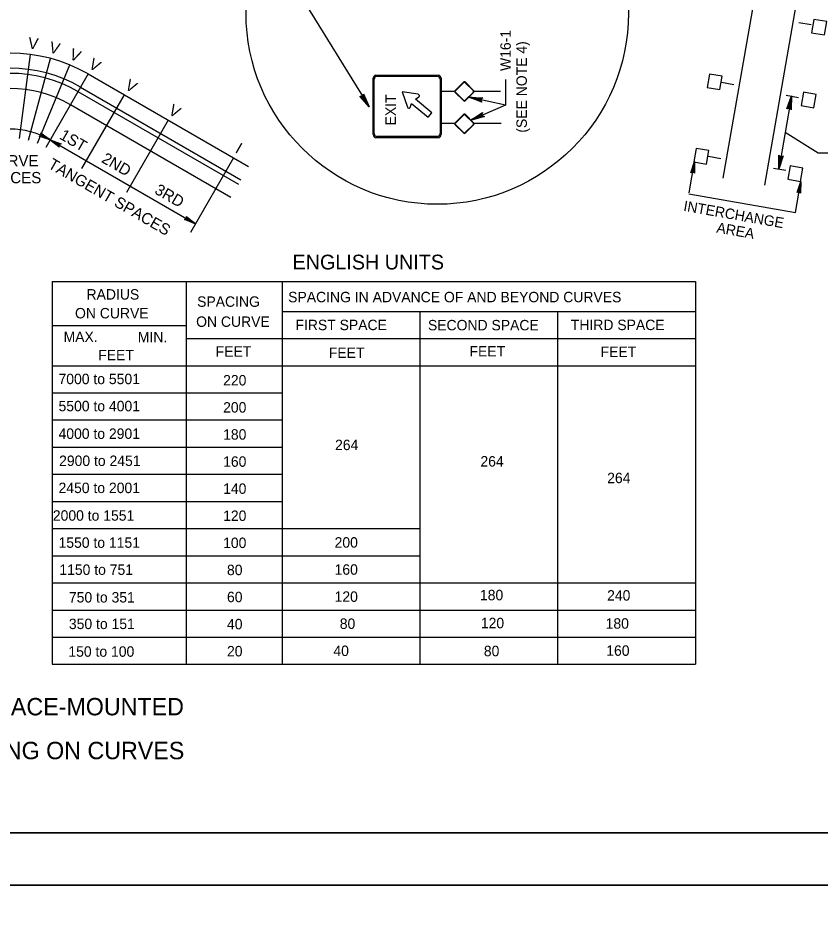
# Model space of a CAD drawing. Extents: x 640253 to 641999, y 298458 to 299646.
# Drawn here: x 641345.5 to 641576.3, y 299044.1 to 299301.1 of the extents above; entities that cross this region are included whole.
import ezdxf

# ---------------------------------------------------------------- set-up
doc = ezdxf.new("R2010")
doc.units = 0
for name, color, linetype in [('1', 7, 'Continuous'), ('2', 7, 'Continuous'), ('PLT-BNDY', 7, 'Continuous')]:
    doc.layers.add(name, color=color, linetype=linetype)

msp = doc.modelspace()

# ---------------------------------------------------------------- linework, layer by layer
at = {"layer": '1'}
for p, q in [((641447.76, 299267.56), (641447.76, 299283.76)), ((641448.05, 299267.83), (641448.05, 299283.49)), ((641448.54, 299284.66), (641466.48, 299284.66)), ((641448.77, 299284.33), (641466.25, 299284.33)), ((641466.97, 299283.49), (641466.97, 299267.83)), ((641467.26, 299283.76), (641467.26, 299267.56)), ((641471.26, 299280.16), (641473.79, 299282.69)), ((641471.39, 299280.15), (641473.81, 299282.56)), ((641474.16, 299282.56), (641476.58, 299280.15)), ((641474.18, 299282.69), (641476.71, 299280.16)), ((641471.18, 299279.96), (641466.97, 299279.96)), ((641484.35, 299279.96), (641476.79, 299279.96)), ((641460.69, 299279.14), (641456.07, 299279.87)), ((641456.07, 299279.87), (641457.61, 299275.45)), ((641459.89, 299277.79), (641460.91, 299278.41)), ((641464.62, 299273.86), (641459.89, 299277.79)), ((641473.79, 299277.24), (641471.26, 299279.77)), ((641473.81, 299277.37), (641471.39, 299279.79)), ((641476.58, 299279.79), (641474.16, 299277.37)), ((641476.71, 299279.77), (641474.18, 299277.24)), ((641458.38, 299275.37), (641458.79, 299276.49)), ((641458.79, 299276.49), (641463.53, 299272.55)), ((641463.53, 299272.55), (641464.62, 299273.86)), ((641471.26, 299270.85), (641473.79, 299273.39)), ((641471.39, 299270.84), (641473.81, 299273.26)), ((641474.16, 299273.26), (641476.58, 299270.84)), ((641474.18, 299273.39), (641476.71, 299270.85)), ((641471.18, 299270.7), (641466.97, 299270.7)), ((641473.79, 299267.93), (641471.26, 299270.47)), ((641473.81, 299268.06), (641471.39, 299270.48)), ((641476.58, 299270.48), (641474.16, 299268.06)), ((641476.71, 299270.47), (641474.18, 299267.93)), ((641484.56, 299270.7), (641476.79, 299270.7)), ((641466.48, 299266.66), (641448.54, 299266.66)), ((641466.25, 299267), (641448.77, 299267)), ((641920.31, 299066.63), (641134.31, 299066.63)), ((641134.31, 299066.63), (641720.31, 299066.63))]:
    msp.add_line(p, q, dxfattribs=at)
for centre, radius, start, end in [((641473.99, 299282.5), 0.275, 45, 135), ((641473.99, 299282.38), 0.252, 45, 135), ((641471.46, 299279.97), 0.275, 135, 225), ((641471.57, 299279.97), 0.252, 135, 225), ((641476.4, 299279.97), 0.252, 315, 45), ((641476.52, 299279.97), 0.275, 315, 45), ((641473.99, 299277.44), 0.275, 225, 315), ((641473.99, 299277.55), 0.252, 225, 315), ((641473.99, 299273.19), 0.275, 45, 135), ((641473.99, 299273.08), 0.252, 45, 135), ((641471.46, 299270.66), 0.275, 135, 225), ((641471.57, 299270.66), 0.252, 135, 225), ((641476.4, 299270.66), 0.252, 315, 45), ((641476.52, 299270.66), 0.275, 315, 45), ((641473.99, 299268.13), 0.275, 225, 315), ((641473.99, 299268.24), 0.252, 225, 315)]:
    msp.add_arc(centre, radius, start, end, dxfattribs=at)
for centre, major_axis, start_param, end_param in [((641448.54, 299283.76), (0, -0.9), 3.141593, 4.712389), ((641448.77, 299283.49), (0, -0.833), 3.141593, 4.712389), ((641466.25, 299283.49), (0, 0.833), 4.712389, 6.283185), ((641466.48, 299283.76), (0, 0.9), 4.712389, 6.283185), ((641460.66, 299278.75), (0.336, -0.279), 6.014589, 8.386103), ((641457.99, 299275.56), (-0.339, 0.282), 1.019875, 3.40872), ((641448.54, 299267.56), (0, -0.9), 4.712389, 6.283185), ((641448.77, 299267.83), (0, -0.833), 4.712389, 6.283185), ((641466.25, 299267.83), (0, 0.833), 3.141593, 4.712389), ((641466.48, 299267.56), (0, 0.9), 3.141593, 4.712389)]:
    msp.add_ellipse(centre, major_axis=major_axis, ratio=0.866667, start_param=start_param, end_param=end_param, dxfattribs=at)
at = {"layer": '2'}
for p, q in [((641548.4, 299255.06), (641564.23, 299345.46)), ((641560.38, 299252.96), (641575.95, 299342.02)), ((641421.94, 299315.4), (641446.55, 299275.57)), ((641570.22, 299299.84), (641570.22, 299299.84)), ((641570.22, 299299.84), (641573.75, 299299.22)), ((641345.98, 299266.45), (641349.15, 299290.63)), ((641348.59, 299265.92), (641354.9, 299289.48)), ((641351.14, 299265.06), (641360.47, 299287.59)), ((641365.73, 299284.99), (641353.56, 299263.87)), ((641365.73, 299284.99), (641411.88, 299258.34)), ((641485.84, 299283.45), (641485.84, 299276.05)), ((641363.56, 299281.22), (641409.71, 299254.58)), ((641551.46, 299281.88), (641547.94, 299282.5)), ((641551.46, 299281.88), (641551.46, 299281.88)), ((641362.81, 299279.93), (641408.96, 299253.29)), ((641376.07, 299279.03), (641363.84, 299257.8)), ((641485.84, 299276.05), (641475.26, 299278.32)), ((641568.09, 299278.74), (641564.39, 299257.61)), ((641566.56, 299278.89), (641566.56, 299278.89)), ((641566.56, 299278.89), (641570.08, 299278.27)), ((641360.64, 299276.17), (641406.79, 299249.53)), ((641485.84, 299276.05), (641475.82, 299271.75)), ((641388.76, 299271.71), (641376.78, 299250.93)), ((641575.72, 299262.19), (641566.24, 299268.18)), ((641354.81, 299266.05), (641396.62, 299241.9)), ((641407.56, 299260.88), (641395.18, 299239.4)), ((641538.63, 299250.84), (641540.19, 299259.77)), ((641547.73, 299260.6), (641544.2, 299261.22)), ((641547.73, 299260.6), (641547.73, 299260.6)), ((641562.9, 299257.94), (641562.9, 299257.94)), ((641562.9, 299257.94), (641566.42, 299257.32)), ((641560.38, 299252.96), (641560.38, 299252.96)), ((641569.2, 299245.13), (641570.76, 299254.06)), ((641538.53, 299250.5), (641569.2, 299245.13)), ((641355.44, 299225.24), (641355.44, 299115.14)), ((641355.44, 299225.24), (641540.45, 299225.24)), ((641393.93, 299225.24), (641393.93, 299115.14)), ((641421.58, 299225.24), (641421.58, 299115.14)), ((641540.45, 299225.24), (641540.45, 299115.14)), ((641421.58, 299216.68), (641540.45, 299216.68)), ((641426.39, 299216.68), (641426.39, 299216.68)), ((641461.18, 299216.68), (641461.18, 299115.14)), ((641461.73, 299216.68), (641461.73, 299216.68)), ((641497.07, 299216.68), (641497.07, 299216.68)), ((641500.78, 299216.68), (641500.78, 299115.14)), ((641532.41, 299216.68), (641532.41, 299216.68)), ((641355.44, 299212.58), (641394, 299212.58)), ((641393.93, 299208.87), (641540.45, 299208.87)), ((641355.44, 299201.06), (641540.45, 299201.06)), ((641355.44, 299193.25), (641421.58, 299193.25)), ((641355.44, 299185.44), (641421.58, 299185.44)), ((641355.44, 299177.63), (641421.58, 299177.63)), ((641355.44, 299169.82), (641421.58, 299169.82)), ((641355.44, 299162.01), (641421.58, 299162.01)), ((641355.44, 299154.2), (641461.18, 299154.2)), ((641355.44, 299146.38), (641461.18, 299146.38)), ((641355.44, 299138.57), (641540.45, 299138.57)), ((641355.44, 299130.76), (641540.45, 299130.76)), ((641355.44, 299122.95), (641540.45, 299122.95)), ((641355.44, 299115.14), (641540.45, 299115.14))]:
    msp.add_line(p, q, dxfattribs=at)
for points in [[(641577.55, 299296.22), (641578.22, 299300.06), (641574.53, 299300.71), (641573.85, 299296.87)], [(641547.5, 299280.48), (641548.17, 299284.32), (641544.48, 299284.97), (641543.81, 299281.13)], [(641574.52, 299275.23), (641575.19, 299279.07), (641571.5, 299279.72), (641570.83, 299275.88)], [(641543.67, 299259.09), (641544.34, 299262.93), (641540.65, 299263.57), (641539.98, 299259.73)], [(641570.69, 299254.04), (641571.36, 299257.88), (641567.67, 299258.53), (641567, 299254.69)]]:
    msp.add_lwpolyline(points, close=True, dxfattribs=at)
for points in [[(641444.9, 299279), (641444.75, 299278.74), (641446.55, 299275.57), (641444.9, 299279), (641444.93, 299279.26), (641446.55, 299275.57), (641444.43, 299278.53), (641444.13, 299278.49), (641446.55, 299275.57), (641443.87, 299278.57), (641444.13, 299278.49)], [(641478.86, 299277.06), (641478.78, 299277.36), (641475.26, 299278.32), (641478.86, 299277.06), (641479.01, 299276.86), (641475.26, 299278.32), (641478.86, 299277.74), (641479.04, 299277.97), (641475.26, 299278.32), (641479.28, 299278.1), (641479.04, 299277.97)], [(641566.97, 299275.09), (641567.26, 299275.18), (641568.09, 299278.74), (641566.97, 299275.09), (641566.77, 299274.93), (641568.09, 299278.74), (641567.64, 299275.12), (641567.88, 299274.94), (641568.09, 299278.74), (641568.03, 299274.71), (641567.88, 299274.94)], [(641479.49, 299272.79), (641479.25, 299272.99), (641475.82, 299271.75), (641479.49, 299272.79), (641479.73, 299272.72), (641475.82, 299271.75), (641479.1, 299273.34), (641479.11, 299273.64), (641475.82, 299271.75), (641479.23, 299273.89), (641479.11, 299273.64)], [(641352.17, 299267.84), (641352.17, 299267.58), (641354.81, 299266.05), (641352.17, 299267.84), (641352.1, 299268.03), (641354.81, 299266.05), (641352.03, 299267.28), (641351.84, 299267.14), (641354.81, 299266.05), (641351.62, 299267.07), (641351.84, 299267.14)], [(641357.34, 299264.12), (641357.36, 299264.38), (641354.81, 299266.05), (641357.34, 299264.12), (641357.41, 299263.93), (641354.81, 299266.05), (641357.52, 299264.66), (641357.73, 299264.8), (641354.81, 299266.05), (641357.95, 299264.85), (641357.73, 299264.8)], [(641608.47, 299262.19), (641575.72, 299262.19)], [(641539.26, 299256.73), (641539.5, 299256.8), (641540.19, 299259.77), (641539.26, 299256.73), (641539.1, 299256.59), (641540.19, 299259.77), (641539.81, 299256.75), (641540.02, 299256.61), (641540.19, 299259.77), (641540.14, 299256.42), (641540.02, 299256.61)], [(641565.51, 299261.26), (641565.22, 299261.17), (641564.39, 299257.61), (641565.51, 299261.26), (641565.71, 299261.42), (641564.39, 299257.61), (641564.84, 299261.23), (641564.6, 299261.41), (641564.39, 299257.61), (641564.45, 299261.64), (641564.6, 299261.41)], [(641569.82, 299251.02), (641570.06, 299251.09), (641570.76, 299254.06), (641569.82, 299251.02), (641569.67, 299250.88), (641570.76, 299254.06), (641570.38, 299251.03), (641570.59, 299250.9), (641570.76, 299254.06), (641570.71, 299250.71), (641570.59, 299250.9)], [(641394.09, 299243.83), (641394.07, 299243.57), (641396.62, 299241.9), (641394.09, 299243.83), (641394.02, 299244.02), (641396.62, 299241.9), (641393.92, 299243.29), (641393.71, 299243.15), (641396.62, 299241.9), (641393.48, 299243.1), (641393.71, 299243.15)]]:
    msp.add_lwpolyline(points, dxfattribs=at)
msp.add_circle((641466.18, 299302.5), 55, dxfattribs=at)
for radius in [44.9, 40.55, 39.07, 34.71, 23.03]:
    msp.add_arc((641343.29, 299246.1), radius, 60.0122, 120.0089, dxfattribs=at)
at = {"layer": 'PLT-BNDY'}
for points in [[(641094.31, 299645.63), (641935.31, 299645.63), (641935.31, 299051.63), (641094.31, 299051.63)], [(641094.31, 299051.63), (641935.31, 299051.63), (641935.31, 298457.63), (641094.31, 298457.63)]]:
    msp.add_lwpolyline(points, close=True, dxfattribs=at)

# ---------------------------------------------------------------- texts
at = {"layer": '1'}
msp.add_text('EXIT', height=3, rotation=90, dxfattribs=at).set_placement((641454.29, 299270.2))
at = {"layer": '2'}
for s, height, rotation, p in [('V', 3.25, 352.4868, (641348.3, 299292.35)), ('W16-1', 3, 90, (641487.32, 299285.85)), ('V', 3.25, 344.9847, (641354.29, 299291.29)), ('(SEE NOTE 4)', 3, 90, (641491.95, 299268.1)), ('V', 3.25, 337.4827, (641360.09, 299289.46)), ('V', 3.25, 330.0028, (641365.62, 299286.91)), ('V', 3.25, 330.0028, (641365.62, 299286.91)), ('V', 3.25, 330.0028, (641376.07, 299280.87)), ('V', 3.25, 330.0028, (641388.59, 299273.65)), ('1ST', 3.246, 329.9971, (641357.26, 299266.5)), ('I', 3.25, 330.0028, (641407.8, 299262.56)), ('2ND', 3.246, 329.9971, (641369.35, 299259.75)), ('TANGENT SPACES', 3.2458, 330, (641353.97, 299258.12)), ('3RD', 3.246, 329.9971, (641384.63, 299250.76)), ('INTERCHANGE', 3, 350.0808, (641536.84, 299245.63)), ('AREA', 3, 350.0808, (641546.35, 299239.4))]:
    msp.add_text(s, height=height, rotation=rotation, dxfattribs=at).set_placement(p)
for s, height, p in [('CURVE', 3.246, (641336.29, 299258.41)), ('SPACES', 3.246, (641334.67, 299253.55)), ('ENGLISH UNITS', 4.25, (641424.55, 299228.75)), ('RADIUS', 3, (641365.29, 299220.08)), ('SPACING', 3, (641397.1, 299218)), ('SPACING IN ADVANCE OF AND BEYOND CURVES', 3, (641423.29, 299219.31)), ('ON CURVE', 3, (641361.98, 299214.67)), ('ON CURVE', 3, (641396.82, 299212.23)), ('FIRST SPACE', 3, (641425.39, 299211.29)), ('SECOND SPACE', 3, (641463.5, 299211.23)), ('THIRD SPACE', 3, (641504.61, 299211.3)), ('MAX.', 3, (641358.69, 299207.86)), ('MIN.', 3, (641380.05, 299207.79)), ('FEET', 3, (641368.65, 299202.62)), ('FEET', 3, (641402.44, 299203.64)), ('FEET', 3, (641435, 299203.28)), ('FEET', 3, (641475.46, 299203.72)), ('FEET', 3, (641513.17, 299203.55)), ('7000 to 5501', 3, (641357.23, 299195.75)), ('220', 3, (641404.58, 299195.37)), ('5500 to 4001', 3, (641357.24, 299187.95)), ('200', 3, (641404.58, 299187.57)), ('4000 to 2901', 3, (641357.24, 299180)), ('180', 3, (641404.58, 299179.78)), ('264', 3, (641436.78, 299176.77)), ('2900 to 2451', 3, (641357.4, 299172.21)), ('160', 3, (641404.58, 299171.98)), ('264', 3, (641478.6, 299172.04)), ('264', 3, (641515.06, 299167.26)), ('2450 to 2001', 3, (641357.24, 299164.41)), ('140', 3, (641404.58, 299164.19)), (' 2000 to 1551', 3, (641354.49, 299156.46)), ('120', 3, (641404.58, 299156.39)), ('1550 to 1151', 3, (641357.24, 299148.66)), ('100', 3, (641404.58, 299148.6)), ('200', 3, (641436.65, 299148.71)), ('1150 to 751', 3, (641357.47, 299140.87)), (' 80', 3, (641404.58, 299140.8)), ('160', 3, (641436.65, 299140.92)), (' 60', 3, (641404.58, 299133.01)), ('120', 3, (641436.65, 299133.12)), ('180', 3, (641478.47, 299133.57)), ('240', 3, (641515.04, 299133.47)), ('750 to 351', 3, (641360.22, 299132.92)), ('350 to 151', 3, (641360.22, 299125.28)), ('80', 3, (641438.14, 299125.33)), ('120', 3, (641478.72, 299125.52)), ('180', 3, (641514.62, 299125.39)), (' 40', 3, (641404.58, 299125.21)), ('160', 3, (641514.8, 299117.59)), ('150 to 100', 3, (641360.07, 299117.32)), (' 20', 3, (641404.58, 299117.42)), (' 40', 3, (641435.19, 299117.53)), (' 80', 3, (641478.47, 299117.47)), ('GROUND/SURFACE-MOUNTED', 5, (641293.76, 299100.46)), ('DELINEATOR SPACING ON CURVES', 5, (641277.13, 299087.84))]:
    msp.add_text(s, height=height, dxfattribs=at).set_placement(p)

doc.saveas('drawing.dxf')
